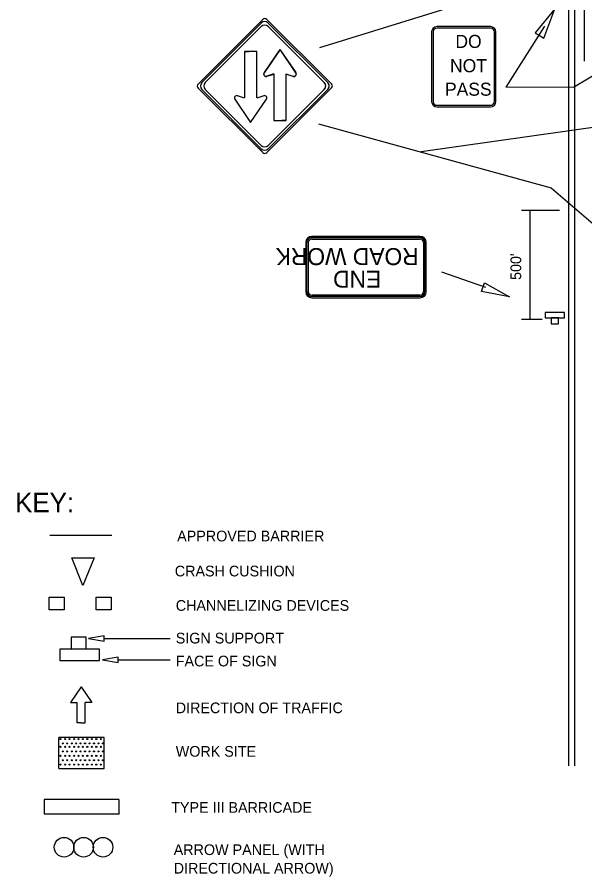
# Model space of a CAD drawing. Extents: x 1531.42 to 1538.58, y 1529.59 to 1539.57.
# Drawn here: x 1531.602 to 1534.782, y 1531.137 to 1535.958 of the extents above; entities that cross this region are included whole.
import ezdxf

# ---------------------------------------------------------------- set-up
doc = ezdxf.new("R2010")
doc.units = 0
for name, color, linetype in [('DETL-DIMS', 7, 'Continuous'), ('DETL-LINE', 7, 'Continuous'), ('DETL-NOTE', 7, 'Continuous'), ('DETL-TITL', 7, 'Continuous'), ('USER-BORD', 7, 'Continuous')]:
    doc.layers.add(name, color=color, linetype=linetype)

# ---------------------------------------------------------------- blocks, each defined once
blk = doc.blocks.new('SIGN13')
at = {"layer": 'USER-BORD'}
for points in [[(-0.0013, 0.0018), (0.0011, 0.0019), (0.0011, 0.0037), (-0.0013, 0.0037)], [(-0.0031, 0.0018), (-0.0031, 0), (0.0032, 0), (0.0032, 0.0018)]]:
    blk.add_lwpolyline(points, close=True, dxfattribs=at)
blk = doc.blocks.new('DIR2')
at = {"layer": 'USER-BORD'}
for p, q in [((0, 0.0001), (-0.0034, -0.0048)), ((0, 0.0001), (0.0034, -0.0048)), ((-0.0034, -0.0048), (-0.0013, -0.0048)), ((-0.0013, -0.0113), (-0.0013, -0.0048)), ((0.0034, -0.0048), (0.0013, -0.0048)), ((0.0013, -0.0113), (0.0013, -0.0048)), ((-0.0001, -0.0113), (-0.0013, -0.0113)), ((-0.0001, -0.0113), (0.0001, -0.0113)), ((0.0001, -0.0113), (0.0013, -0.0113))]:
    blk.add_line(p, q, dxfattribs=at)
blk = doc.blocks.new('PANEL0')
at = {"layer": 'USER-BORD'}
for centre in [(0.00309, -0.00012), (0.00928, -0.00012), (0.01546, -0.00012)]:
    blk.add_circle(centre, 0.00312, dxfattribs=at)
blk = doc.blocks.new('R-BRD3')
at = {"layer": 'USER-BORD'}
for p, q in [((1.415, 2.996), (-1.412, 2.996)), ((-1.3, 2.95), (1.3, 2.95)), ((-1.5, 2.909), (-1.5, 0.087)), ((-1.45, 0.2), (-1.45, 2.8)), ((-1.375, 2.725), (-1.375, 0.275)), ((1.225, 2.875), (-1.225, 2.875)), ((1.375, 0.275), (1.375, 2.725)), ((1.45, 2.8), (1.45, 0.2)), ((1.502, 0.087), (1.502, 2.909)), ((-1.412, 0), (1.415, 0)), ((1.3, 0.05), (-1.3, 0.05)), ((-1.225, 0.125), (1.225, 0.125))]:
    blk.add_line(p, q, dxfattribs=at)
for centre, radius, start, end in [((-1.412, 2.909), 0.0875, 90, 180), ((-1.3, 2.8), 0.15, 90, 180), ((1.3, 2.8), 0.15, 0, 90), ((1.415, 2.909), 0.0875, 0, 90), ((-1.225, 2.725), 0.15, 90, 180), ((1.225, 2.725), 0.15, 0, 90), ((-1.225, 0.275), 0.15, 180, 270), ((1.225, 0.275), 0.15, 270, 0), ((-1.412, 0.087), 0.0875, 180, 270), ((-1.3, 0.2), 0.15, 180, 270), ((1.3, 0.2), 0.15, 270, 0), ((1.415, 0.087), 0.0875, 270, 0)]:
    blk.add_arc(centre, radius, start, end, dxfattribs=at)
blk = doc.blocks.new('W-BRD1')
at = {"layer": 'USER-BORD', "rotation": 45}
blk.add_blockref('R-BRD3', (1.0448, 1.0213), dxfattribs=at)

msp = doc.modelspace()

# ---------------------------------------------------------------- linework, layer by layer
at = {"layer": 'DETL-DIMS'}
for p, q in [((1533.297, 1535.7885), (1534.5672, 1536.1813)), ((1534.5557, 1535.9083), (1534.339, 1535.5665)), ((1534.9116, 1535.6801), (1534.7186, 1535.5639)), ((1534.7195, 1535.5639), (1534.339, 1535.5665)), ((1533.8643, 1535.2045), (1535.0172, 1535.3683)), ((1533.2891, 1535.3595), (1534.5927, 1535.0002)), ((1534.5927, 1535.0002), (1535.0146, 1534.6391)), ((1534.6394, 1534.8742), (1534.4271, 1534.8742)), ((1534.4738, 1534.8742), (1534.4738, 1534.2647)), ((1533.9788, 1534.5298), (1534.2245, 1534.4435)), ((1534.4271, 1534.2647), (1534.5425, 1534.2647)), ((1532.0882, 1532.4741), (1532.4582, 1532.4741)), ((1532.1675, 1532.3543), (1532.4582, 1532.3543))]:
    msp.add_line(p, q, dxfattribs=at)
for points in [[(1534.5029, 1535.8695), (1534.5531, 1535.8405), (1534.6147, 1536.0052)], [(1534.2025, 1534.4197), (1534.2201, 1534.4691), (1534.3602, 1534.3898)], [(1532.0882, 1532.4591), (1532.0882, 1532.4882), (1532.0002, 1532.4741)], [(1532.1675, 1532.3393), (1532.1675, 1532.3693), (1532.0794, 1532.3543)]]:
    msp.add_lwpolyline(points, close=True, dxfattribs=at)
at = {"layer": 'DETL-LINE'}
for p, q in [((1534.6905, 1536.28), (1534.6905, 1531.7597)), ((1534.724, 1536.28), (1534.724, 1531.7597)), ((1534.7777, 1536.28), (1534.7777, 1535.711)), ((1532.9781, 1535.946), (1532.6153, 1535.5832)), ((1533.3625, 1535.584), (1533.0005, 1535.946)), ((1532.6357, 1535.5917), (1532.9693, 1535.9253)), ((1532.9693, 1535.9253), (1532.6357, 1535.5917)), ((1532.6549, 1535.5917), (1532.9692, 1535.9061)), ((1533.0077, 1535.9061), (1533.3221, 1535.5917)), ((1533.0078, 1535.9253), (1533.3414, 1535.5917)), ((1533.3414, 1535.5917), (1533.0078, 1535.9253)), ((1534.2536, 1535.9053), (1533.9538, 1535.9053)), ((1534.2536, 1535.8968), (1533.9538, 1535.8968)), ((1533.9237, 1535.8752), (1533.9237, 1535.4854)), ((1533.9322, 1535.8752), (1533.9322, 1535.4854)), ((1534.2752, 1535.4854), (1534.2752, 1535.8752)), ((1534.2837, 1535.4854), (1534.2837, 1535.8752)), ((1532.8985, 1535.7661), (1532.8754, 1535.7661)), ((1532.8754, 1535.7661), (1532.8754, 1535.5731)), ((1532.9435, 1535.7663), (1532.8767, 1535.7663)), ((1532.8767, 1535.7663), (1532.8985, 1535.7661)), ((1532.9435, 1535.5731), (1532.9435, 1535.7663)), ((1533.0732, 1535.7777), (1532.9844, 1535.6473)), ((1533.0744, 1535.777), (1532.9855, 1535.6466)), ((1533.0732, 1535.7777), (1533.162, 1535.6473)), ((1533.1632, 1535.6466), (1533.0744, 1535.777)), ((1533.0393, 1535.64), (1532.9996, 1535.6271)), ((1533.0007, 1535.6264), (1533.0404, 1535.6393)), ((1533.0392, 1535.6398), (1533.0392, 1535.5718)), ((1533.0403, 1535.6391), (1533.0403, 1535.5711)), ((1533.1072, 1535.64), (1533.1468, 1535.6271)), ((1533.1072, 1535.6398), (1533.1072, 1535.5718)), ((1533.1083, 1535.6393), (1533.148, 1535.6264)), ((1533.1084, 1535.5711), (1533.1084, 1535.6391)), ((1532.6153, 1535.5608), (1532.9772, 1535.1988)), ((1532.9693, 1535.2196), (1532.6357, 1535.5532)), ((1532.6357, 1535.5532), (1532.9693, 1535.2196)), ((1532.9693, 1535.2389), (1532.6549, 1535.5532)), ((1532.8754, 1535.5731), (1532.8754, 1535.505)), ((1532.9435, 1535.505), (1532.9435, 1535.5731)), ((1532.9997, 1535.1988), (1533.3625, 1535.5615)), ((1533.3414, 1535.5532), (1533.0078, 1535.2196)), ((1533.3221, 1535.5532), (1533.0078, 1535.2389)), ((1533.0078, 1535.2196), (1533.3414, 1535.5532)), ((1533.0392, 1535.5718), (1533.0392, 1535.3785)), ((1533.0403, 1535.5711), (1533.0403, 1535.3779)), ((1533.1072, 1535.5718), (1533.1072, 1535.3787)), ((1533.1084, 1535.378), (1533.1084, 1535.5711)), ((1532.8755, 1535.5048), (1532.8358, 1535.5177)), ((1532.9831, 1535.5177), (1532.9434, 1535.5048)), ((1532.8207, 1535.4975), (1532.9095, 1535.3671)), ((1532.9095, 1535.3671), (1532.9983, 1535.4975)), ((1533.9538, 1535.4638), (1534.2536, 1535.4638)), ((1533.9538, 1535.4553), (1534.2536, 1535.4553)), ((1532.9093, 1535.3674), (1532.9108, 1535.3689)), ((1533.0392, 1535.3785), (1533.106, 1535.3785)), ((1533.0403, 1535.3779), (1533.1072, 1535.3779)), ((1533.1072, 1535.3787), (1533.0842, 1535.3787)), ((1533.0853, 1535.378), (1533.1084, 1535.378)), ((1533.1072, 1535.3779), (1533.0853, 1535.378)), ((1533.1032, 1535.3785), (1533.1072, 1535.3826)), ((1533.2179, 1534.6942), (1533.2179, 1534.4186)), ((1533.2249, 1534.4186), (1533.2249, 1534.6942)), ((1533.2329, 1534.4186), (1533.2329, 1534.6942)), ((1533.8586, 1534.7287), (1533.2525, 1534.7287)), ((1533.2525, 1534.7218), (1533.8586, 1534.7218)), ((1533.2525, 1534.7139), (1533.8586, 1534.7139)), ((1533.8787, 1534.6942), (1533.8787, 1534.4186)), ((1533.8859, 1534.6942), (1533.8859, 1534.4186)), ((1533.8929, 1534.4186), (1533.8929, 1534.6942)), ((1533.2327, 1534.4188), (1533.2329, 1534.4186)), ((1533.8586, 1534.3987), (1533.2525, 1534.3987)), ((1533.8586, 1534.3913), (1533.2525, 1534.3913)), ((1533.2525, 1534.3843), (1533.8586, 1534.3843)), ((1531.7835, 1533.0528), (1532.1323, 1533.0528)), ((1532.0894, 1531.9187), (1531.8354, 1531.9187)), ((1532.0894, 1531.9187), (1531.8354, 1531.9187)), ((1532.0894, 1531.9187), (1531.8354, 1531.9187)), ((1532.0894, 1531.9187), (1531.8354, 1531.9187)), ((1531.8355, 1531.7446), (1531.8355, 1531.9186)), ((1531.8355, 1531.7446), (1531.8355, 1531.9186)), ((1531.844, 1531.9098), (1531.844, 1531.9098)), ((1531.8448, 1531.9098), (1531.8448, 1531.9098)), ((1531.8696, 1531.9098), (1531.8696, 1531.9098)), ((1531.8696, 1531.9098), (1531.8696, 1531.9098)), ((1531.8944, 1531.9098), (1531.8944, 1531.9098)), ((1531.8952, 1531.9098), (1531.8952, 1531.9098)), ((1531.9192, 1531.9098), (1531.9192, 1531.9098)), ((1531.92, 1531.9098), (1531.92, 1531.9098)), ((1531.944, 1531.9098), (1531.944, 1531.9098)), ((1531.9448, 1531.9098), (1531.9448, 1531.9098)), ((1531.9696, 1531.9098), (1531.9696, 1531.9098)), ((1531.9696, 1531.9098), (1531.9696, 1531.9098)), ((1531.9944, 1531.9098), (1531.9944, 1531.9098)), ((1531.9944, 1531.9098), (1531.9944, 1531.9098)), ((1532.0192, 1531.9098), (1532.0192, 1531.9098)), ((1532.02, 1531.9098), (1532.02, 1531.9098)), ((1532.044, 1531.9098), (1532.044, 1531.9098)), ((1532.0448, 1531.9098), (1532.0448, 1531.9098)), ((1532.0696, 1531.9098), (1532.0696, 1531.9098)), ((1532.0696, 1531.9098), (1532.0696, 1531.9098)), ((1532.0894, 1531.7447), (1532.0894, 1531.9187)), ((1532.0894, 1531.7447), (1532.0894, 1531.9187)), ((1532.0894, 1531.7447), (1532.0894, 1531.9187)), ((1532.0894, 1531.7447), (1532.0894, 1531.9187)), ((1531.844, 1531.866), (1531.844, 1531.866)), ((1531.8448, 1531.866), (1531.8448, 1531.866)), ((1531.8568, 1531.885), (1531.8568, 1531.885)), ((1531.8568, 1531.885), (1531.8568, 1531.885)), ((1531.8568, 1531.8404), (1531.8568, 1531.8404)), ((1531.8696, 1531.866), (1531.8696, 1531.866)), ((1531.8696, 1531.866), (1531.8696, 1531.866)), ((1531.8816, 1531.885), (1531.8816, 1531.885)), ((1531.8816, 1531.885), (1531.8816, 1531.885)), ((1531.8816, 1531.8404), (1531.8816, 1531.8404)), ((1531.8944, 1531.866), (1531.8944, 1531.866)), ((1531.8952, 1531.866), (1531.8952, 1531.866)), ((1531.9072, 1531.885), (1531.9072, 1531.885)), ((1531.9072, 1531.885), (1531.9072, 1531.885)), ((1531.9072, 1531.8404), (1531.9072, 1531.8404)), ((1531.9192, 1531.866), (1531.9192, 1531.866)), ((1531.92, 1531.866), (1531.92, 1531.866)), ((1531.932, 1531.885), (1531.932, 1531.885)), ((1531.932, 1531.885), (1531.932, 1531.885)), ((1531.932, 1531.8404), (1531.932, 1531.8404)), ((1531.944, 1531.866), (1531.944, 1531.866)), ((1531.9448, 1531.866), (1531.9448, 1531.866)), ((1531.9568, 1531.885), (1531.9568, 1531.885)), ((1531.9568, 1531.885), (1531.9568, 1531.885)), ((1531.9568, 1531.8404), (1531.9568, 1531.8404)), ((1531.9696, 1531.866), (1531.9696, 1531.866)), ((1531.9696, 1531.866), (1531.9696, 1531.866)), ((1531.9816, 1531.885), (1531.9816, 1531.885)), ((1531.9816, 1531.885), (1531.9816, 1531.885)), ((1531.9816, 1531.8404), (1531.9816, 1531.8404)), ((1531.9944, 1531.866), (1531.9944, 1531.866)), ((1531.9944, 1531.866), (1531.9944, 1531.866)), ((1532.0064, 1531.885), (1532.0064, 1531.885)), ((1532.0064, 1531.885), (1532.0064, 1531.885)), ((1532.0064, 1531.8404), (1532.0064, 1531.8404)), ((1532.0192, 1531.866), (1532.0192, 1531.866)), ((1532.02, 1531.866), (1532.02, 1531.866)), ((1532.032, 1531.885), (1532.032, 1531.885)), ((1532.032, 1531.885), (1532.032, 1531.885)), ((1532.032, 1531.8404), (1532.032, 1531.8404)), ((1532.044, 1531.866), (1532.044, 1531.866)), ((1532.0448, 1531.866), (1532.0448, 1531.866)), ((1532.0568, 1531.885), (1532.0568, 1531.885)), ((1532.0568, 1531.885), (1532.0568, 1531.885)), ((1532.0568, 1531.8404), (1532.0568, 1531.8404)), ((1532.0696, 1531.866), (1532.0696, 1531.866)), ((1532.0696, 1531.866), (1532.0696, 1531.866)), ((1532.0816, 1531.885), (1532.0816, 1531.885)), ((1532.0816, 1531.885), (1532.0816, 1531.885)), ((1532.0816, 1531.8404), (1532.0816, 1531.8404)), ((1531.844, 1531.8156), (1531.844, 1531.8156)), ((1531.8448, 1531.8156), (1531.8448, 1531.8156)), ((1531.8696, 1531.8156), (1531.8696, 1531.8156)), ((1531.8696, 1531.8156), (1531.8696, 1531.8156)), ((1531.8944, 1531.8156), (1531.8944, 1531.8156)), ((1531.8952, 1531.8156), (1531.8952, 1531.8156)), ((1531.9192, 1531.8156), (1531.9192, 1531.8156)), ((1531.92, 1531.8156), (1531.92, 1531.8156)), ((1531.944, 1531.8156), (1531.944, 1531.8156)), ((1531.9448, 1531.8156), (1531.9448, 1531.8156)), ((1531.9696, 1531.8156), (1531.9696, 1531.8156)), ((1531.9696, 1531.8156), (1531.9696, 1531.8156)), ((1531.9944, 1531.8156), (1531.9944, 1531.8156)), ((1531.9944, 1531.8156), (1531.9944, 1531.8156)), ((1532.0192, 1531.8156), (1532.0192, 1531.8156)), ((1532.02, 1531.8156), (1532.02, 1531.8156)), ((1532.044, 1531.8156), (1532.044, 1531.8156)), ((1532.0448, 1531.8156), (1532.0448, 1531.8156)), ((1532.0696, 1531.8156), (1532.0696, 1531.8156)), ((1532.0696, 1531.8156), (1532.0696, 1531.8156)), ((1531.8355, 1531.7446), (1532.0894, 1531.7446)), ((1531.844, 1531.7664), (1531.844, 1531.7664)), ((1531.8448, 1531.7664), (1531.8448, 1531.7664)), ((1531.8568, 1531.7908), (1531.8568, 1531.7908)), ((1531.8568, 1531.7908), (1531.8568, 1531.7908)), ((1531.8696, 1531.7664), (1531.8696, 1531.7664)), ((1531.8696, 1531.7664), (1531.8696, 1531.7664)), ((1531.8816, 1531.7908), (1531.8816, 1531.7908)), ((1531.8816, 1531.7908), (1531.8816, 1531.7908)), ((1531.8944, 1531.7664), (1531.8944, 1531.7664)), ((1531.8952, 1531.7664), (1531.8952, 1531.7664)), ((1531.9072, 1531.7908), (1531.9072, 1531.7908)), ((1531.9072, 1531.7908), (1531.9072, 1531.7908)), ((1531.9192, 1531.7664), (1531.9192, 1531.7664)), ((1531.92, 1531.7664), (1531.92, 1531.7664)), ((1531.932, 1531.7908), (1531.932, 1531.7908)), ((1531.932, 1531.7908), (1531.932, 1531.7908)), ((1531.944, 1531.7664), (1531.944, 1531.7664)), ((1531.9448, 1531.7664), (1531.9448, 1531.7664)), ((1531.9568, 1531.7908), (1531.9568, 1531.7908)), ((1531.9568, 1531.7908), (1531.9568, 1531.7908)), ((1531.9696, 1531.7664), (1531.9696, 1531.7664)), ((1531.9696, 1531.7664), (1531.9696, 1531.7664)), ((1531.9816, 1531.7908), (1531.9816, 1531.7908)), ((1531.9816, 1531.7908), (1531.9816, 1531.7908)), ((1531.9944, 1531.7664), (1531.9944, 1531.7664)), ((1531.9944, 1531.7664), (1531.9944, 1531.7664)), ((1532.0064, 1531.7908), (1532.0064, 1531.7908)), ((1532.0064, 1531.7908), (1532.0064, 1531.7908)), ((1532.0192, 1531.7664), (1532.0192, 1531.7664)), ((1532.02, 1531.7664), (1532.02, 1531.7664)), ((1532.032, 1531.7908), (1532.032, 1531.7908)), ((1532.032, 1531.7908), (1532.032, 1531.7908)), ((1532.044, 1531.7664), (1532.044, 1531.7664)), ((1532.0448, 1531.7664), (1532.0448, 1531.7664)), ((1532.0568, 1531.7908), (1532.0568, 1531.7908)), ((1532.0568, 1531.7908), (1532.0568, 1531.7908)), ((1532.0696, 1531.7664), (1532.0696, 1531.7664)), ((1532.0696, 1531.7664), (1532.0696, 1531.7664)), ((1532.0816, 1531.7908), (1532.0816, 1531.7908)), ((1532.0816, 1531.7908), (1532.0816, 1531.7908)), ((1531.7518, 1531.5709), (1531.7518, 1531.4899)), ((1532.1737, 1531.5709), (1531.7518, 1531.5709)), ((1532.1737, 1531.4881), (1532.1737, 1531.5691)), ((1531.7518, 1531.4899), (1532.1737, 1531.4899))]:
    msp.add_line(p, q, dxfattribs=at)
for points in [[(1534.6687, 1534.2716), (1534.6687, 1534.3025), (1534.5605, 1534.3025), (1534.5605, 1534.2716)], [(1534.6351, 1534.2716), (1534.5938, 1534.2716), (1534.5938, 1534.2389), (1534.6351, 1534.2389)], [(1531.9068, 1532.9268), (1532.0327, 1532.9268), (1531.9702, 1532.7709)], [(1531.7808, 1532.6344), (1531.7808, 1532.7057), (1531.8654, 1532.7057), (1531.8654, 1532.6344)], [(1532.0442, 1532.6344), (1532.0442, 1532.7057), (1532.1288, 1532.7057), (1532.1288, 1532.6344)]]:
    msp.add_lwpolyline(points, close=True, dxfattribs=at)
for centre in [(1531.8448, 1531.9096), (1531.8696, 1531.9096), (1531.8952, 1531.9096), (1531.92, 1531.9096), (1531.9448, 1531.9096), (1531.9696, 1531.9096), (1531.9944, 1531.9096), (1532.02, 1531.9096), (1532.0448, 1531.9096), (1532.0696, 1531.9096), (1531.8448, 1531.8659), (1531.8568, 1531.8848), (1531.8568, 1531.8403), (1531.8696, 1531.8659), (1531.8816, 1531.8848), (1531.8816, 1531.8403), (1531.8952, 1531.8659), (1531.9072, 1531.8848), (1531.9072, 1531.8403), (1531.92, 1531.8659), (1531.932, 1531.8848), (1531.932, 1531.8403), (1531.9448, 1531.8659), (1531.9568, 1531.8848), (1531.9568, 1531.8403), (1531.9696, 1531.8659), (1531.9816, 1531.8848), (1531.9816, 1531.8403), (1531.9944, 1531.8659), (1532.0064, 1531.8848), (1532.0064, 1531.8403), (1532.02, 1531.8659), (1532.032, 1531.8848), (1532.032, 1531.8403), (1532.0448, 1531.8659), (1532.0568, 1531.8848), (1532.0568, 1531.8403), (1532.0696, 1531.8659), (1532.0816, 1531.8848), (1532.0816, 1531.8403), (1531.8448, 1531.8155), (1531.8568, 1531.7907), (1531.8696, 1531.8155), (1531.8816, 1531.7907), (1531.8952, 1531.8155), (1531.9072, 1531.7907), (1531.92, 1531.8155), (1531.932, 1531.7907), (1531.9448, 1531.8155), (1531.9568, 1531.7907), (1531.9696, 1531.8155), (1531.9816, 1531.7907), (1531.9944, 1531.8155), (1532.0064, 1531.7907), (1532.02, 1531.8155), (1532.032, 1531.7907), (1532.0448, 1531.8155), (1532.0568, 1531.7907), (1532.0696, 1531.8155), (1532.0816, 1531.7907), (1531.8448, 1531.7663), (1531.8696, 1531.7663), (1531.8952, 1531.7663), (1531.92, 1531.7663), (1531.9448, 1531.7663), (1531.9696, 1531.7663), (1531.9944, 1531.7663), (1532.02, 1531.7663), (1532.0448, 1531.7663), (1532.0696, 1531.7663)]:
    msp.add_circle(centre, 0.00291, dxfattribs=at)
for centre, radius, start, end in [((1532.9893, 1535.9348), 0.0159, 45, 135), ((1532.9885, 1535.8868), 0.0272, 45, 135), ((1532.9885, 1535.906), 0.0272, 45, 135), ((1532.9885, 1535.906), 0.0272, 45, 135), ((1533.9537, 1535.8753), 0.03, 90, 180), ((1533.9537, 1535.8753), 0.0215, 90, 180), ((1534.2537, 1535.8753), 0.03, 0, 90), ((1534.2537, 1535.8753), 0.0215, 0, 90), ((1532.9954, 1535.6398), 0.0134, 145.7397, 288), ((1532.9966, 1535.6391), 0.0134, 145.7397, 288), ((1533.151, 1535.6398), 0.0134, 252, 34.2603), ((1533.1521, 1535.6391), 0.0134, 252, 34.2603), ((1532.6265, 1535.572), 0.0159, 135, 225), ((1532.6549, 1535.5725), 0.0272, 135, 225), ((1532.6549, 1535.5725), 0.0272, 135, 225), ((1532.6741, 1535.5725), 0.0272, 135, 225), ((1533.3028, 1535.5725), 0.0272, 315, 45), ((1533.3221, 1535.5725), 0.0272, 315, 45), ((1533.3221, 1535.5725), 0.0272, 315, 45), ((1533.3513, 1535.5728), 0.0159, 315, 45), ((1532.8317, 1535.505), 0.0134, 72, 214.2603), ((1532.9873, 1535.505), 0.0134, 325.7397, 108), ((1533.9537, 1535.4853), 0.03, 180, 270), ((1533.9537, 1535.4853), 0.0215, 180, 270), ((1534.2537, 1535.4853), 0.03, 270, 0), ((1534.2537, 1535.4853), 0.0215, 270, 0), ((1532.9885, 1535.2581), 0.0272, 225, 315), ((1532.9885, 1535.2389), 0.0272, 225, 315), ((1532.9885, 1535.2389), 0.0272, 225, 315), ((1532.9885, 1535.21), 0.0159, 225, 315), ((1533.2525, 1534.6943), 0.0345, 90, 180), ((1533.2525, 1534.6943), 0.0276, 90, 180), ((1533.2525, 1534.6943), 0.0198, 90, 180), ((1533.8585, 1534.6943), 0.0345, 0, 90), ((1533.8585, 1534.6943), 0.0276, 0, 90), ((1533.8585, 1534.6943), 0.0198, 0, 90), ((1533.2525, 1534.4188), 0.0345, 180, 270), ((1533.2525, 1534.4188), 0.0276, 180, 270), ((1533.2525, 1534.4188), 0.0198, 180, 270), ((1533.8585, 1534.4188), 0.0345, 270, 0), ((1533.8585, 1534.4188), 0.0276, 270, 0), ((1533.8585, 1534.4188), 0.0198, 270, 0)]:
    msp.add_arc(centre, radius, start, end, dxfattribs=at)

# ---------------------------------------------------------------- block references
for name, p, xscale, yscale in [('W-BRD1', (1532.9914, 1535.1947), 0.1814448, 0.18144479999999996), ('SIGN13', (1531.9499, 1532.3506), 35.23199999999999, 35.23199999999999), ('DIR2', (1531.9596, 1532.2), 17.615999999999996, 17.615999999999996), ('PANEL0', (1531.8099, 1531.3049), 17.615999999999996, 17.615999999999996)]:
    msp.add_blockref(name, p, dxfattribs=dict(at, xscale=xscale, yscale=yscale))

# ---------------------------------------------------------------- texts
for s, p in [('DO', (1534.0568, 1535.7856)), ('NOT', (1534.0265, 1535.6495)), ('PASS', (1533.9984, 1535.5176))]:
    msp.add_text(s, height=0.07326, dxfattribs=at).set_placement(p)
for s, p in [('ROAD WORK', (1533.8508, 1534.6631)), ('END', (1533.641, 1534.5363))]:
    msp.add_text(s, height=0.09541, rotation=180, dxfattribs=at).set_placement(p)
at = {"layer": 'DETL-NOTE'}
msp.add_text("500'", height=0.06, rotation=90, dxfattribs=at).set_placement((1534.4254, 1534.4844))
for s, p in [('APPROVED BARRIER', (1532.4978, 1533.0182)), ('CRASH CUSHION', (1532.4846, 1532.8218)), ('CHANNELIZING DEVICES', (1532.4899, 1532.6289)), ('SIGN SUPPORT', (1532.4899, 1532.4457)), ('FACE OF SIGN', (1532.4899, 1532.3171)), ('DIRECTION OF TRAFFIC', (1532.4899, 1532.0546)), ('WORK SITE', (1532.4899, 1531.8106)), ('TYPE III BARRICADE', (1532.4643, 1531.496)), ('ARROW PANEL (WITH', (1532.4784, 1531.2591)), ('DIRECTIONAL ARROW)', (1532.4784, 1531.1551))]:
    msp.add_text(s, height=0.06, dxfattribs=at).set_placement(p)
at = {"layer": 'DETL-TITL'}
msp.add_text('KEY:', height=0.10852, dxfattribs=at).set_placement((1531.5897, 1533.182))

doc.saveas('drawing.dxf')
